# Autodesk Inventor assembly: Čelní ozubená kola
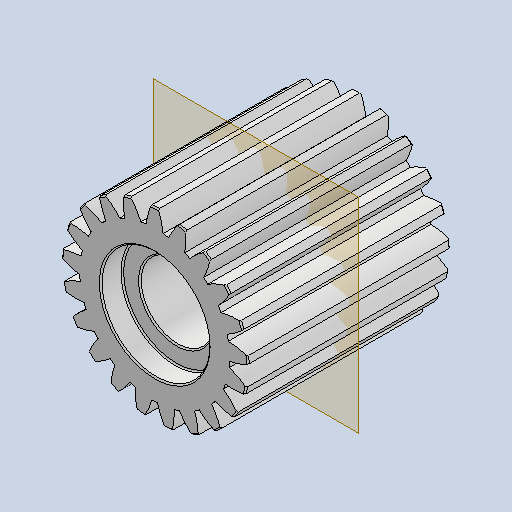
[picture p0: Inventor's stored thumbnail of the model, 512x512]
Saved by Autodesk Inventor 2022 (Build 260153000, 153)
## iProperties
ClientObjectVersion: 1
Created: 2025-05
Part Number: Čelní ozubená kola
Document SubType Name: Assembly
Designer: jbart
Categories: <?xml version="1.0" encoding="UTF-16"?> <MemberInstance><Categories><FamilyTemplate/><ParamToTemplateMap><ParamToTemplate><ParamToTemplate CategoryParameter="//
Author: jbart
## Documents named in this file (2)
- C:\Users\jbart\OneDrive\Dokumenty\Inventor\Převodovka navijáku\Satelit A\Design Accelerator\Čelní ozubená kola1.iam
- C:\Users\jbart\OneDrive\Dokumenty\Inventor\Převodovka navijáku\Satelit A\Design Accelerator\Čelní ozubené kolo11.ipt
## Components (1 placed, 1 different names)
1. Čelní ozubené kolo1:1
